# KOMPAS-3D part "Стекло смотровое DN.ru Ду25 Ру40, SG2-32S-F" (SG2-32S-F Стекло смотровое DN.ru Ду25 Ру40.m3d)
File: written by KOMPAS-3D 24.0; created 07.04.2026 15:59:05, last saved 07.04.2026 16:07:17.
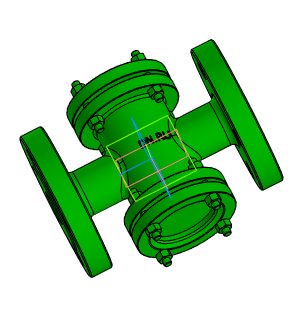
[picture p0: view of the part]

Document properties: Автор: Main; Полное имя файла: D:\DN.ru Аутсерс\Стекло смотровое DN.ru\SG2-32S-F Стекло смотровое DN.ru Ду25 Ру40\SG2-32S-F Стекло смотровое DN.ru Ду25 Ру40.m3d

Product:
- Body: Тело 1  | qty 1
    Масса: 4.394636
- Part/product: Стекло смотровое DN.ru Ду25 Ру40  | designation SG2-32S-F
    Масса: 5.5
    Раздел спецификации: Прочие изделия
    Примечание: D500-00105

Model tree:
1. Операция без истории:1

Expressions: SG2-32S-F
